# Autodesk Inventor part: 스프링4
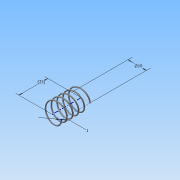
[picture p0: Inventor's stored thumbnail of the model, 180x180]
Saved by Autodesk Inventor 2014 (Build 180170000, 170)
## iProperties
Created: 2015-06
Part Number: 스프링4
Material: Generic
Document SubType Name: Modeling
Designer: Administrator
Density: 1 g/cm^3
Appearance: Default
Author: Administrator
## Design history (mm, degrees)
sketch "스케치1"
  geometry: L1 (0, 0)-(8, 0); L2 (8, 0)-(8, 14.5); L3 (8, 14.5)-(0, 14.5); L4 (0, 14.5)-(0, 0); C1 r 0.5 at (8, 0)
  constraints: 8 end point, 2 parallel, 1 centre point, 1 coincident, 1 horizontal, 1 perpendicular
  dimensions: "d0" = 14.5 distance of L3.end L1.start (derived); "d1" = 16 diameter of L2 L4; "d2" = 1 diameter of C1
feature "코일1" sketch "스케치1" pitch "d3" = 10; turns "d5" = 5; dims "d4" = 14.5 (= d0), "d6" = 0, angle "d7" = 90 deg, angle "d8" = 90 deg, "d9" = 0, "d10" = 0
sketch "스케치2"
  geometry: L1 (-8.5, 0)-(-7.5, 0) reference; 1 further point
  constraints: 1 horizontal alignment
extrude "돌출1" cut sketch "스케치2" stored distance "d11" = 10; taper "d12" = 0 deg
node "작업 평면1"
sketch "스케치3"
  geometry: L1 (-7.5, 0)-(-8.5, 0) reference; 1 further point
  constraints: 1 horizontal alignment
extrude "돌출2" cut sketch "스케치3" stored distance "d14" = 10; taper "d15" = 0 deg
node "솔리드1"
node "절단 모서리 투영1"
node "절단 모서리 투영2"
other parameters: "d13" = 14.5 (= d0)
